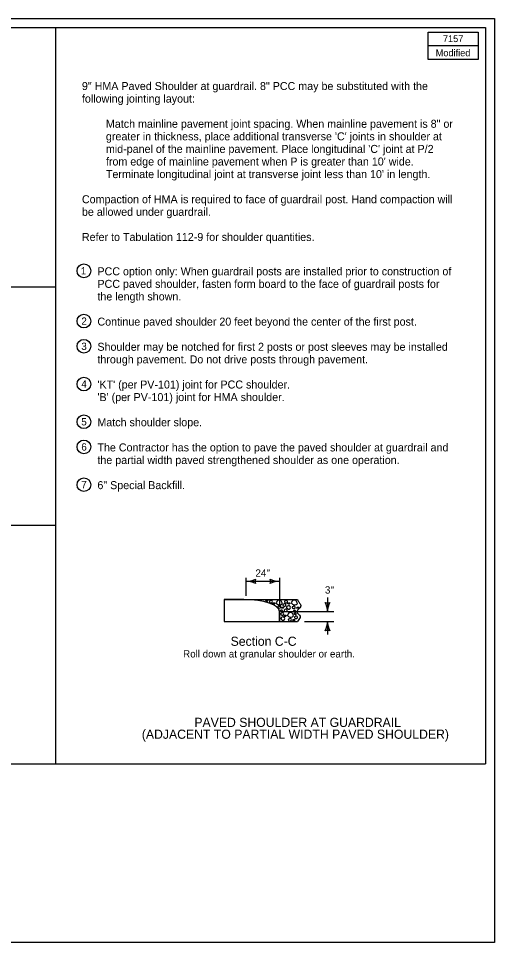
# Model space of a CAD drawing. Extents: x 8045 to 81668, y 6217 to 16762.
# Drawn here: x 12226 to 13268, y 7924 to 9944 of the extents above; entities that cross this region are included whole.
import ezdxf

# ---------------------------------------------------------------- set-up
doc = ezdxf.new("R2010")
doc.units = 0
for name, color, linetype in [('dsnCellElements', 7, 'Continuous'), ('dsnStdCells', 7, 'Continuous'), ('dsnStdDimension', 7, 'Continuous'), ('dsnStdLabel', 7, 'Continuous'), ('dsnStdLineWork', 7, 'Continuous'), ('dsnStdNote', 7, 'Continuous'), ('dsnStdPattern', 7, 'Continuous'), ('dsnStdSection', 7, 'Continuous'), ('Level 4', 7, 'Continuous'), ('Level 8', 7, 'Continuous')]:
    doc.layers.add(name, color=color, linetype=linetype)

msp = doc.modelspace()

# ---------------------------------------------------------------- linework, layer by layer
at = {"layer": 'dsnCellElements'}
for p, q in [((12724.6, 8682.2), (12724.6, 8721.5)), ((12724.6, 8713.6), (12797.2, 8713.6)), ((12797.2, 8721.5), (12797.2, 8658)), ((12902.3, 8678.4), (12902.3, 8647.5)), ((12804, 8647.5), (12916.1, 8647.5)), ((12852, 8625.7), (12916.1, 8625.7)), ((12902.3, 8625.7), (12902.3, 8597.1))]:
    msp.add_line(p, q, dxfattribs=at)
for centre, radius, start, end in [((12724.6, 8756.1), 42.5, 270, 298.0725), ((12724.6, 8671.1), 42.5, 61.9275, 90), ((12760.3, 8713.6), 16.4, 162.2666, 197.7334), ((12761.5, 8713.6), 16.4, 342.2666, 17.7334), ((12797.2, 8756.1), 42.5, 241.9275, 270), ((12797.2, 8671.1), 42.5, 90, 118.0725), ((12902.3, 8683.1), 16.4, 252.2666, 287.7334), ((12859.8, 8647.5), 42.5, 0, 28.0725), ((12944.8, 8647.5), 42.5, 151.9275, 180), ((12859.8, 8625.7), 42.5, 331.9275, 360), ((12944.8, 8625.7), 42.5, 180, 208.0725), ((12902.3, 8590), 16.4, 72.2666, 107.7334)]:
    msp.add_arc(centre, radius, start, end, dxfattribs=at)
at = {"layer": 'dsnStdCells'}
for points in [[(12768.9, 8669.4), (12769.8, 8669.2), (12770.3, 8669.2), (12772.7, 8671.6), (12768.7, 8672.4), (12765.2, 8670.3), (12768.1, 8669.6), (12768.9, 8669.4)], [(12775.4, 8669.9), (12775.4, 8670.5), (12775.8, 8670.3), (12780.3, 8673), (12782.7, 8669.8), (12780.6, 8665.7), (12775.5, 8666.8), (12775.3, 8669.3), (12775.4, 8669.9)], [(12784.6, 8663.9), (12785.4, 8663.7), (12785.9, 8663.7), (12788.4, 8666.1), (12784.3, 8666.9), (12780.9, 8664.8), (12783.7, 8664.1), (12784.6, 8663.9)], [(12790.2, 8666.1), (12790, 8666.6), (12790.5, 8666.3), (12792.4, 8672.7), (12800.7, 8673), (12803.4, 8665.7), (12803.6, 8664.9), (12798.8, 8661.2), (12792.1, 8663.3), (12790.5, 8665.7), (12790.2, 8666.1)], [(12808.3, 8669.9), (12808.3, 8670.5), (12808.7, 8670.3), (12813.3, 8673), (12815.7, 8669.8), (12813.5, 8665.7), (12808.4, 8666.8), (12808.3, 8669.3), (12808.3, 8669.9)], [(12817.5, 8663.9), (12818.3, 8663.7), (12818.9, 8663.7), (12821.3, 8666.1), (12817.3, 8666.9), (12813.8, 8664.8), (12816.6, 8664.1), (12817.5, 8663.9)], [(12823.2, 8666.1), (12822.9, 8666.6), (12823.4, 8666.3), (12825.3, 8672.7), (12833.6, 8673), (12836.3, 8665.7), (12836.6, 8664.9), (12831.7, 8661.2), (12825, 8663.3), (12823.4, 8665.7), (12823.2, 8666.1)], [(12793.7, 8658.7), (12793.8, 8659.2), (12794.1, 8659.1), (12798.7, 8661.7), (12801.1, 8658.5), (12799, 8654.5), (12793.9, 8655.6), (12793.7, 8658.1), (12793.7, 8658.7)], [(12799.1, 8649), (12798.7, 8649.5), (12799.1, 8649.8), (12803.4, 8651.2), (12804.7, 8647.7), (12801.5, 8646.9), (12799.5, 8648.5), (12799.1, 8649)], [(12803.9, 8654.7), (12804.7, 8654.5), (12805.2, 8654.5), (12807.6, 8656.9), (12803.6, 8657.7), (12800.1, 8655.6), (12803, 8654.8), (12803.9, 8654.7)], [(12804.8, 8662.7), (12804.8, 8663.3), (12805.2, 8663.1), (12809.7, 8665.8), (12812.1, 8662.6), (12810, 8658.6), (12804.9, 8659.7), (12804.7, 8662.2), (12804.8, 8662.7)], [(12807.6, 8650.9), (12807.7, 8651.5), (12808, 8651.3), (12812.6, 8654), (12815, 8650.8), (12812.8, 8646.8), (12807.8, 8647.8), (12807.6, 8650.3), (12807.6, 8650.9)], [(12812.8, 8656.7), (12812.3, 8657.9), (12812.4, 8658.2), (12817, 8661.2), (12821, 8659.3), (12822.1, 8654), (12815.9, 8651.3), (12813.4, 8655.6), (12812.8, 8656.7)], [(12814.7, 8639), (12814.5, 8639.5), (12815, 8639.2), (12816.9, 8645.6), (12825.2, 8645.8), (12827.9, 8638.6), (12828.1, 8637.8), (12823.3, 8634.1), (12816.6, 8636.2), (12815, 8638.5), (12814.7, 8639)], [(12825, 8657.3), (12825.1, 8657.9), (12825.4, 8657.7), (12830, 8660.4), (12832.4, 8657.2), (12830.3, 8653.2), (12825.2, 8654.3), (12825, 8656.8), (12825, 8657.3)], [(12827.8, 8648.6), (12827.4, 8649), (12827.7, 8649.4), (12832, 8650.7), (12833.3, 8647.3), (12830.1, 8646.5), (12828.2, 8648.1), (12827.8, 8648.6)], [(12836.8, 8654.7), (12837.6, 8654.5), (12838.2, 8654.5), (12840.6, 8656.9), (12836.6, 8657.7), (12833.1, 8655.6), (12835.9, 8654.8), (12836.8, 8654.7)], [(12800.3, 8632.2), (12799.7, 8633.4), (12799.9, 8633.7), (12804.4, 8636.7), (12808.5, 8634.8), (12809.5, 8629.4), (12803.4, 8626.8), (12800.9, 8631), (12800.3, 8632.2)], [(12799.9, 8642.8), (12799.9, 8643.3), (12800.3, 8643.2), (12804.8, 8645.8), (12807.2, 8642.6), (12805.1, 8638.6), (12800, 8639.7), (12799.8, 8642.2), (12799.9, 8642.8)], [(12809.1, 8636.8), (12809.9, 8636.6), (12810.5, 8636.6), (12812.9, 8639), (12808.9, 8639.8), (12805.4, 8637.7), (12808.2, 8637), (12809.1, 8636.8)], [(12816.6, 8630.2), (12816.7, 8630.8), (12817, 8630.6), (12821.6, 8633.3), (12824, 8630.1), (12821.8, 8626.1), (12816.8, 8627.1), (12816.6, 8629.6), (12816.6, 8630.2)], [(12828.4, 8627.5), (12829.2, 8627.4), (12829.7, 8627.4), (12832.2, 8629.8), (12828.1, 8630.6), (12824.7, 8628.4), (12827.5, 8627.7), (12828.4, 8627.5)], [(12829.1, 8642.5), (12828.7, 8643), (12829, 8643.3), (12833.3, 8644.7), (12834.6, 8641.2), (12831.4, 8640.4), (12829.5, 8642), (12829.1, 8642.5)], [(12830.2, 8635.6), (12830.2, 8636.2), (12830.6, 8636), (12835.2, 8638.7), (12837.6, 8635.5), (12835.4, 8631.5), (12830.3, 8632.6), (12830.2, 8635.1), (12830.2, 8635.6)]]:
    msp.add_open_spline(points, degree=3, dxfattribs=at)
at = {"layer": 'dsnStdDimension'}
for p, q in [((10152.2, 9924.4), (13247.9, 9924.4)), ((13247.9, 9924.4), (13247.9, 8314.4)), ((10152.2, 8314.4), (13247.9, 8314.4))]:
    msp.add_line(p, q, dxfattribs=at)
at = {"layer": 'dsnStdLabel'}
for p, q in [((13247.9, 9924.4), (13247.9, 9924.4)), ((12676.2, 8673.7), (12676.2, 8625.7)), ((12676.2, 8673.7), (12719.3, 8673.6)), ((12719.3, 8673.6), (12837, 8673.6)), ((12797.2, 8647.5), (12797.2, 8625.7)), ((12676.2, 8625.7), (12797.2, 8625.7)), ((12797.2, 8625.7), (12837, 8625.7))]:
    msp.add_line(p, q, dxfattribs=at)
msp.add_ellipse((12719.3, 8647.5), major_axis=(77.9, 0), ratio=0.335273, start_param=0, end_param=1.570796, dxfattribs=at)
msp.add_spline([(12837, 8673.6), (12838.4, 8670.4), (12840.3, 8667.3), (12842.2, 8664.2), (12843.6, 8661.1), (12843.7, 8659.4), (12843, 8657.6), (12840.2, 8654.2), (12837, 8650.7), (12835.9, 8648.9), (12835.6, 8648), (12835.5, 8647.2), (12835.5, 8646.8), (12835.8, 8645.6), (12836.8, 8644), (12839.8, 8640.8), (12842.3, 8637.6), (12842.7, 8636), (12842.6, 8635.3), (12842.5, 8634.9), (12842.3, 8634.5), (12837, 8625.7)], degree=3, dxfattribs=at)
at = {"layer": 'dsnStdLineWork'}
msp.add_lwpolyline([(13232.1, 9914.4), (13232.1, 9854.4), (13122.1, 9854.4), (13122.1, 9914.4), (13232.1, 9914.4), (13232.1, 9884.4), (13122.1, 9884.4)], dxfattribs=at)
at = {"layer": 'dsnStdPattern'}
for p, q in [((12719.3, 8673.7), (12676.2, 8673.7)), ((12676.2, 8673.7), (12676.2, 8625.7)), ((12797.2, 8625.7), (12797.2, 8647.5)), ((12676.2, 8625.7), (12797.2, 8625.7))]:
    msp.add_line(p, q, dxfattribs=at)
msp.add_lwpolyline([(12719.3, 8673.6), (12719.3, 8673.7)], dxfattribs=at)
msp.add_ellipse((12719.3, 8647.5), major_axis=(77.9, 0), ratio=0.335273, start_param=0, end_param=1.570796, dxfattribs=at)
at = {"layer": 'dsnStdSection'}
msp.add_lwpolyline([(10132.5, 9944), (13267.5, 9944), (13267.5, 7924), (10132.5, 7924)], close=True, dxfattribs=at)
at = {"layer": 'Level 4'}
for p, q in [((12307.8, 8314.4), (12307.8, 9924.4)), ((12307.8, 9356.4), (10152.2, 9356.4)), ((12307.8, 8835.4), (10152.2, 8835.4))]:
    msp.add_line(p, q, dxfattribs=at)
at = {"layer": 'Level 8'}
for centre in [(12369.6, 9392.4), (12369.6, 9282.4), (12369.6, 9227.4), (12369.6, 9144.9), (12369.6, 9062.4), (12369.6, 9007.4), (12369.6, 8924.9)]:
    msp.add_circle(centre, 15, dxfattribs=at)

# ---------------------------------------------------------------- texts
at = {"layer": 'dsnCellElements'}
for s, p in [("24''", (12744.7, 8723.8)), ("3'' ", (12896.6, 8686.8))]:
    msp.add_text(s, height=16, dxfattribs=at).set_placement(p)
at = {"layer": 'dsnStdLineWork'}
for s, p in [('7157', (13154.7, 9892.4)), ('Modified', (13138.9, 9861.4))]:
    msp.add_text(s, height=15, dxfattribs=at).set_placement(p)
at = {"layer": 'dsnStdNote'}
for s, height, p in [('Section C-C', 20, (12690.4, 8572.6)), ('Roll down at granular shoulder or earth.', 16, (12586.5, 8547.1)), ('PAVED SHOULDER AT GUARDRAIL', 20, (12611.1, 8395.3)), ('(ADJACENT TO PARTIAL WIDTH PAVED SHOULDER)', 20, (12496.2, 8369.4))]:
    msp.add_text(s, height=height, dxfattribs=at).set_placement(p)
at = {"layer": 'Level 8'}
for s, height, p in [('9" HMA Paved Shoulder at guardrail. 8" PCC may be substituted with the', 17.5, (12365.2, 9787.6)), ('following jointing layout:', 17.5, (12365.2, 9760.1)), ('Match mainline pavement joint spacing. When mainline pavement is 8" or ', 17.5, (12417.7, 9705.1)), ("greater in thickness, place additional transverse 'C' joints in shoulder at ", 17.5, (12417.7, 9677.6)), ("mid-panel of the mainline pavement. Place longitudinal 'C' joint at P/2 ", 17.5, (12417.7, 9650.1)), ("from edge of mainline pavement when P is greater than 10' wide. ", 17.5, (12417.7, 9622.6)), ("Terminate longitudinal joint at transverse joint less than 10' in length.", 17.5, (12417.7, 9595.1)), ('Compaction of HMA is required to face of guardrail post. Hand compaction will ', 17.5, (12365.2, 9540.1)), ('be allowed under guardrail. ', 17.5, (12365.2, 9512.6)), ('Refer to Tabulation 112-9 for shoulder quantities.', 17.5, (12365.2, 9457.6)), ('1', 16, (12362.8, 9384.4)), ('PCC option only: When guardrail posts are installed prior to construction of ', 17.5, (12399.1, 9382.6)), ('PCC paved shoulder, fasten form board to the face of guardrail posts for ', 17.5, (12399.1, 9355.1)), ('the length shown.', 17.5, (12399.1, 9327.6)), ('2', 16, (12364, 9274.4)), ('Continue paved shoulder 20 feet beyond the center of the first post.', 17.5, (12399.1, 9272.6)), ('3', 16, (12363.9, 9219.4)), ('Shoulder may be notched for first 2 posts or post sleeves may be installed ', 17.5, (12399.1, 9217.6)), ('through pavement. Do not drive posts through pavement.', 17.5, (12399.1, 9190.1)), ('4', 16, (12363.9, 9136.9)), ("'KT' (per PV-101) joint for PCC shoulder.", 17.5, (12399.1, 9135.1)), ("'B' (per PV-101) joint for HMA shoulder.", 17.5, (12399.1, 9107.6)), ('5', 16, (12363.8, 9054.4)), ('Match shoulder slope.', 17.5, (12399.1, 9052.6)), ('6', 16, (12363.9, 8999.4)), ('The Contractor has the option to pave the paved shoulder at guardrail and ', 17.5, (12399.1, 8997.6)), ('the partial width paved strengthened shoulder as one operation.', 17.5, (12399.1, 8970.1)), ('7', 16, (12363.9, 8916.9)), ('6" Special Backfill.', 17.5, (12399.1, 8915.1))]:
    msp.add_text(s, height=height, dxfattribs=at).set_placement(p)

doc.saveas('drawing.dxf')
